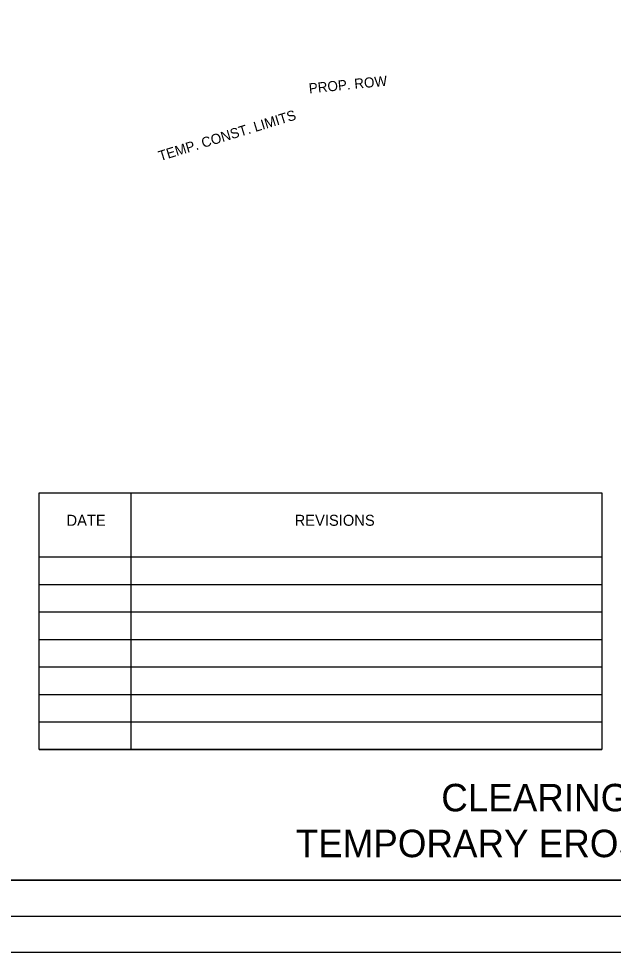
# Model space of a CAD drawing. Extents: x 7675 to 14104, y 9961 to 11168.
# Drawn here: x 9203 to 9528, y 9961 to 10470 of the extents above; entities that cross this region are included whole.
import ezdxf

# ---------------------------------------------------------------- set-up
doc = ezdxf.new("R2010")
doc.units = 0
for name, color, linetype in [('Clearing and Grubbing Temp Seeding', 7, 'Continuous'), ('GREEN_TXT', 7, 'Continuous'), ('R_ROW Annot Labels Ends', 7, 'Continuous'), ('S_WALL', 7, 'Continuous'), ('SEAL-INFO', 7, 'Continuous'), ('Stage 1 Ditch Checks', 7, 'Continuous'), ('Stage 2 Construction', 7, 'Continuous')]:
    doc.layers.add(name, color=color, linetype=linetype)

msp = doc.modelspace()

# ---------------------------------------------------------------- linework, layer by layer
at = {"layer": 'Clearing and Grubbing Temp Seeding'}
for p, q in [((9264.37, 10211.28), (9264.37, 10071.28)), ((9264.37, 10211.28), (9521.39, 10211.28)), ((9214.37, 10176.28), (9521.39, 10176.28)), ((9214.37, 10161.28), (9521.39, 10161.28)), ((9214.37, 10146.28), (9521.39, 10146.28)), ((9214.37, 10131.28), (9521.39, 10131.28)), ((9214.37, 10116.28), (9521.39, 10116.28)), ((9214.37, 10101.28), (9521.39, 10101.28)), ((9214.37, 10086.28), (9521.39, 10086.28)), ((9214.37, 10071.28), (9521.39, 10071.28))]:
    msp.add_line(p, q, dxfattribs=at)
msp.add_lwpolyline([(9214.37, 10211.28), (9521.39, 10211.28), (9521.39, 10071.28), (9214.37, 10071.28)], close=True, dxfattribs=at)
at = {"layer": 'GREEN_TXT'}
for p, q in [((9811.58, 10000), (8230.68, 10000)), ((8074.58, 9960.6), (9834.58, 9960.6))]:
    msp.add_line(p, q, dxfattribs=at)
at = {"layer": 'SEAL-INFO'}
msp.add_lwpolyline([(8168.64, 11046.77), (9835.34, 11046.77), (9835.34, 9980.09), (8168.64, 9980.09)], close=True, dxfattribs=at)
at = {"layer": 'Stage 1 Ditch Checks'}
msp.add_lwpolyline([(8230.68, 10000), (9811.58, 10000), (9810.97, 10963.3), (9596.08, 10963.3), (9587.98, 10959.87), (9579.17, 10961.4), (9578.94, 10977.9), (9400.28, 10977.9), (9400.28, 11027.3), (8230.68, 11027.3)], close=True, dxfattribs=at)
msp.add_lwpolyline([(8230.68, 10000), (9811.58, 10000), (9810.97, 10963.3), (9596.08, 10963.3), (9587.98, 10959.87), (9579.17, 10961.4), (9578.94, 10977.9), (9400.28, 10977.9), (9400.28, 11027.3), (8230.68, 11027.3)], close=True, dxfattribs=at)
msp.add_lwpolyline([(8230.68, 10000), (9811.58, 10000), (9810.97, 10963.3), (9596.08, 10963.3), (9587.98, 10959.87), (9579.17, 10961.4), (9578.94, 10977.9), (9400.28, 10977.9), (9400.28, 11027.3), (8230.68, 11027.3)], close=True, dxfattribs=at)
msp.add_lwpolyline([(8230.68, 10000), (9811.58, 10000), (9810.97, 10963.3), (9596.08, 10963.3), (9587.98, 10959.87), (9579.17, 10961.4), (9578.94, 10977.9), (9400.28, 10977.9), (9400.28, 11027.3), (8230.68, 11027.3)], close=True, dxfattribs=at)
msp.add_lwpolyline([(8230.68, 10000), (9811.58, 10000), (9810.97, 10963.3), (9596.08, 10963.3), (9587.98, 10959.87), (9579.17, 10961.4), (9578.94, 10977.9), (9400.28, 10977.9), (9400.28, 11027.3), (8230.68, 11027.3)], close=True, dxfattribs=at)

# ---------------------------------------------------------------- texts
at = {"layer": 'GREEN_TXT'}
for s, p in [('CLEARING AND GRUBBING ', (9433.84, 10037.5)), ('TEMPORARY EROSION CONTROL DETAILS', (9354.41, 10012.5))]:
    msp.add_text(s, height=15, dxfattribs=at).set_placement(p)
at = {"layer": 'R_ROW Annot Labels Ends'}
msp.add_text('PROP. ROW', height=5.5, rotation=5.6793, dxfattribs=at).set_placement((9361.83, 10429.13))
at = {"layer": 'S_WALL'}
for s, p in [('DATE', (9229.37, 10193.28)), ('  REVISIONS', (9349.37, 10193.28))]:
    msp.add_text(s, height=6, dxfattribs=at).set_placement(p)
at = {"layer": 'Stage 2 Construction'}
msp.add_text('TEMP. CONST. LIMITS', height=5.5, rotation=17.0142, dxfattribs=at).set_placement((9280.47, 10392.19))

doc.saveas('drawing.dxf')
